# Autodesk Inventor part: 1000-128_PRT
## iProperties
Created: 2006-10
Part Number: 1000-128_PRT
Document SubType Name: Modeling
Designer: Andy Moles
Density: 7.85 g/cm^3
Material: Steel
Mass: 32.7061 g
Surface Area: 20.709 cm^2
Volume: 4.16639 cm^3
Author: Andy Moles
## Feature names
1. Base1
